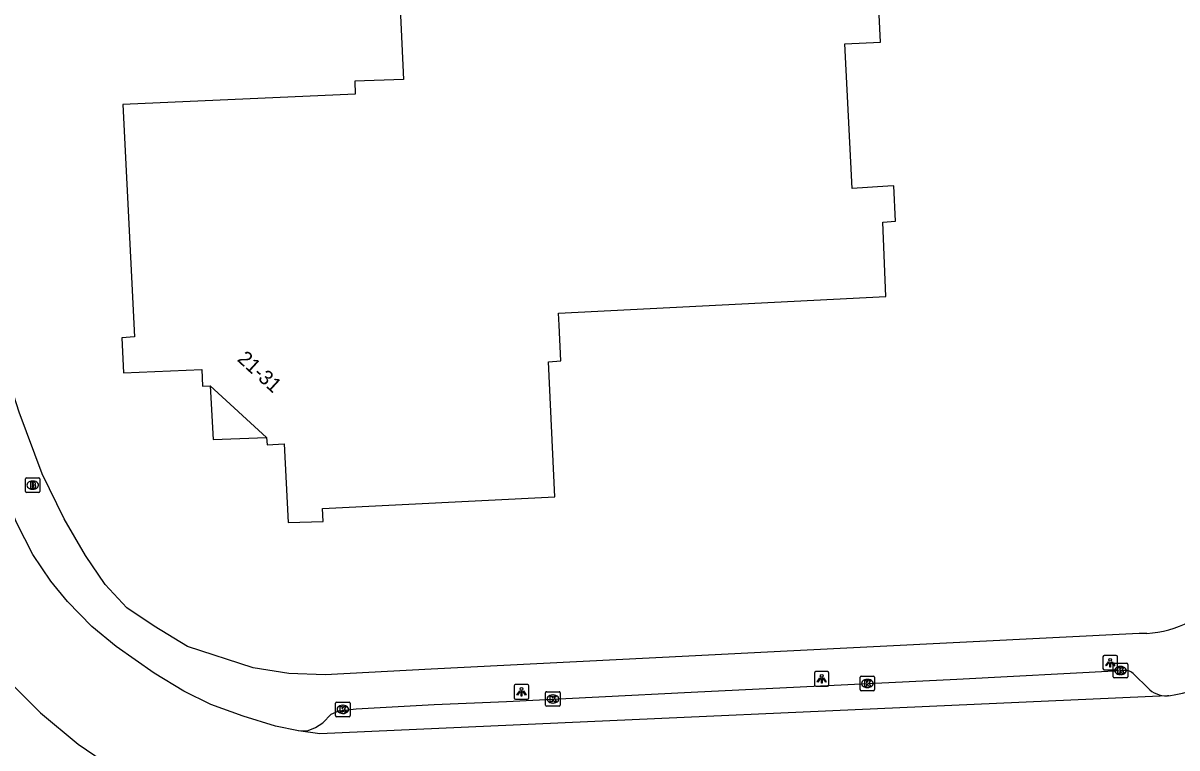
# Model space of a CAD drawing. Extents: x 157692 to 159670, y 381454 to 383289.
# Drawn here: x 157922.9 to 158002.1, y 381592.8 to 381642.5 of the extents above; entities that cross this region are included whole.
import ezdxf

# ---------------------------------------------------------------- set-up
doc = ezdxf.new("R2010")
doc.units = 0
for name, color, linetype in [('IMGEO_Brandkraan', 7, 'Continuous'), ('IMGEO_Kolk', 7, 'Continuous'), ('IMGEO_Lichtpunt', 7, 'Continuous'), ('IMGEO_Pand', 7, 'Continuous'), ('IMGEO_Pand_nummerreeks', 7, 'Continuous'), ('IMGEO_Pand_overbouw', 7, 'Continuous'), ('IMGEO_Rijbaan_lokaal_gesloten', 7, 'Continuous'), ('IMGEO_Voetpad_open', 7, 'Continuous')]:
    doc.layers.add(name, color=color, linetype=linetype)

msp = doc.modelspace()

# ---------------------------------------------------------------- linework, layer by layer
at = {"layer": 'IMGEO_Brandkraan'}
for p, q in [((157923.045, 381610.378), (157923.045, 381611.23)), ((157923.12, 381611.304), (157923.972, 381611.304)), ((157923.533, 381611.084), (157923.558, 381611.084)), ((157924.046, 381611.23), (157924.046, 381610.378)), ((157923.972, 381610.304), (157923.12, 381610.304)), ((157923.556, 381610.524), (157923.531, 381610.524))]:
    msp.add_line(p, q, dxfattribs=at)
for points in [[(157923.045, 381610.378), (157923.045, 381611.23)], [(157923.12, 381611.304), (157923.972, 381611.304)], [(157923.393, 381611.004), (157923.393, 381610.604), (157923.606, 381610.604)], [(157923.624, 381611.004), (157923.393, 381611.004)], [(157923.572, 381610.923), (157923.518, 381610.923), (157923.518, 381610.847)], [(157923.518, 381610.847), (157923.571, 381610.847)], [(157923.58, 381610.771), (157923.518, 381610.771), (157923.518, 381610.69)], [(157924.046, 381611.23), (157924.046, 381610.378)], [(157923.972, 381610.304), (157923.12, 381610.304)], [(157923.518, 381610.69), (157923.58, 381610.69)]]:
    msp.add_lwpolyline(points, dxfattribs=at)
for centre, radius, start, end in [((157923.122, 381611.228), 0.0765, 91.55205, 178.44795), ((157923.122, 381611.228), 0.0765, 91.55205, 178.44795), ((157923.573, 381610.885), 0.0379, 267.82845, 90.93552), ((157923.581, 381610.73), 0.0404, 269.87594, 90.50774), ((157923.628, 381610.859), 0.145, 59.4692, 91.53667), ((157923.653, 381610.906), 0.0922, 285.51372, 58.15012), ((157923.658, 381610.714), 0.105, 301.31148, 78.98903), ((157923.97, 381611.228), 0.0765, 1.55205, 88.44795), ((157923.97, 381611.228), 0.0765, 1.55205, 88.44795), ((157923.122, 381610.38), 0.0765, 181.55205, 268.44795), ((157923.122, 381610.38), 0.0765, 181.55205, 268.44795), ((157923.612, 381610.855), 0.251, 268.66757, 293.53466), ((157923.97, 381610.38), 0.0765, 271.55205, 358.44795), ((157923.97, 381610.38), 0.0765, 271.55205, 358.44795)]:
    msp.add_arc(centre, radius, start, end, dxfattribs=at)
for centre, major_axis, ratio, start_param, end_param in [((157923.532, 381610.804), (-0.387, 0.002), 0.722429, 4.712389, 7.853982), ((157923.557, 381610.804), (-0.39, 0.002), 0.717154, 1.570796, 4.712389)]:
    msp.add_ellipse(centre, major_axis=major_axis, ratio=ratio, start_param=start_param, end_param=end_param, dxfattribs=at)
at = {"layer": 'IMGEO_Kolk'}
for p, q in [((157997.701, 381597.653), (157997.701, 381598.505)), ((157997.776, 381598.579), (157998.628, 381598.579)), ((157998.189, 381598.359), (157998.214, 381598.359)), ((157998.702, 381598.505), (157998.702, 381597.653)), ((157980.327, 381596.768), (157980.327, 381597.62)), ((157980.402, 381597.694), (157981.254, 381597.694)), ((157980.815, 381597.474), (157980.84, 381597.474)), ((157981.328, 381597.62), (157981.328, 381596.768)), ((157998.628, 381597.579), (157997.776, 381597.579)), ((157998.212, 381597.799), (157998.187, 381597.799)), ((157958.749, 381595.703), (157958.749, 381596.555)), ((157958.824, 381596.629), (157959.676, 381596.629)), ((157959.75, 381596.555), (157959.75, 381595.703)), ((157981.254, 381596.694), (157980.402, 381596.694)), ((157980.838, 381596.914), (157980.813, 381596.914)), ((157944.331, 381594.987), (157944.331, 381595.839)), ((157944.406, 381595.913), (157945.258, 381595.913)), ((157944.819, 381595.693), (157944.844, 381595.693)), ((157945.332, 381595.839), (157945.332, 381594.987)), ((157959.26, 381595.849), (157959.235, 381595.849)), ((157959.237, 381596.409), (157959.262, 381596.409)), ((157945.258, 381594.913), (157944.406, 381594.913)), ((157944.842, 381595.133), (157944.817, 381595.133)), ((157959.676, 381595.629), (157958.824, 381595.629))]:
    msp.add_line(p, q, dxfattribs=at)
for points in [[(157997.701, 381597.653), (157997.701, 381598.505)], [(157997.776, 381598.579), (157998.628, 381598.579)], [(157998.022, 381598.279), (157998.145, 381598.279), (157998.145, 381598.128), (157998.275, 381598.279), (157998.439, 381598.279), (157998.293, 381598.128), (157998.446, 381597.879), (157998.294, 381597.879), (157998.209, 381598.043), (157998.145, 381597.976), (157998.145, 381597.879), (157998.022, 381597.879), (157998.022, 381598.279)], [(157998.702, 381598.505), (157998.702, 381597.653)], [(157980.327, 381596.768), (157980.327, 381597.62)], [(157980.402, 381597.694), (157981.254, 381597.694)], [(157980.648, 381597.394), (157980.771, 381597.394), (157980.771, 381597.243), (157980.901, 381597.394), (157981.065, 381597.394), (157980.919, 381597.243), (157981.072, 381596.994), (157980.92, 381596.994), (157980.835, 381597.158), (157980.771, 381597.091), (157980.771, 381596.994), (157980.648, 381596.994), (157980.648, 381597.394)], [(157981.328, 381597.62), (157981.328, 381596.768)], [(157998.628, 381597.579), (157997.776, 381597.579)], [(157958.749, 381595.703), (157958.749, 381596.555)], [(157958.824, 381596.629), (157959.676, 381596.629)], [(157959.75, 381596.555), (157959.75, 381595.703)], [(157981.254, 381596.694), (157980.402, 381596.694)], [(157944.331, 381594.987), (157944.331, 381595.839)], [(157944.406, 381595.913), (157945.258, 381595.913)], [(157945.332, 381595.839), (157945.332, 381594.987)], [(157959.07, 381596.329), (157959.193, 381596.329), (157959.193, 381596.178), (157959.323, 381596.329), (157959.487, 381596.329), (157959.341, 381596.178), (157959.494, 381595.929), (157959.342, 381595.929), (157959.257, 381596.093), (157959.193, 381596.026), (157959.193, 381595.929), (157959.07, 381595.929), (157959.07, 381596.329)], [(157945.258, 381594.913), (157944.406, 381594.913)], [(157944.652, 381595.613), (157944.775, 381595.613), (157944.775, 381595.462), (157944.905, 381595.613), (157945.069, 381595.613), (157944.923, 381595.462), (157945.076, 381595.213), (157944.924, 381595.213), (157944.839, 381595.377), (157944.775, 381595.31), (157944.775, 381595.213), (157944.652, 381595.213), (157944.652, 381595.613)], [(157959.676, 381595.629), (157958.824, 381595.629)]]:
    msp.add_lwpolyline(points, dxfattribs=at)
for centre, start, end in [((157997.778, 381598.503), 91.55205, 178.44795), ((157997.778, 381598.503), 91.55205, 178.44795), ((157998.626, 381598.503), 1.55205, 88.44795), ((157998.626, 381598.503), 1.55205, 88.44795), ((157980.404, 381597.618), 91.55205, 178.44795), ((157980.404, 381597.618), 91.55205, 178.44795), ((157981.252, 381597.618), 1.55205, 88.44795), ((157981.252, 381597.618), 1.55205, 88.44795), ((157997.778, 381597.655), 181.55205, 268.44795), ((157997.778, 381597.655), 181.55205, 268.44795), ((157998.626, 381597.655), 271.55205, 358.44795), ((157998.626, 381597.655), 271.55205, 358.44795), ((157958.826, 381596.553), 91.55205, 178.44795), ((157958.826, 381596.553), 91.55205, 178.44795), ((157959.674, 381596.553), 1.55205, 88.44795), ((157959.674, 381596.553), 1.55205, 88.44795), ((157980.404, 381596.77), 181.55205, 268.44795), ((157980.404, 381596.77), 181.55205, 268.44795), ((157981.252, 381596.77), 271.55205, 358.44795), ((157981.252, 381596.77), 271.55205, 358.44795), ((157944.408, 381595.837), 91.55205, 178.44795), ((157944.408, 381595.837), 91.55205, 178.44795), ((157945.256, 381595.837), 1.55205, 88.44795), ((157945.256, 381595.837), 1.55205, 88.44795), ((157958.826, 381595.705), 181.55205, 268.44795), ((157958.826, 381595.705), 181.55205, 268.44795), ((157959.674, 381595.705), 271.55205, 358.44795), ((157959.674, 381595.705), 271.55205, 358.44795), ((157944.408, 381594.989), 181.55205, 268.44795), ((157944.408, 381594.989), 181.55205, 268.44795), ((157945.256, 381594.989), 271.55205, 358.44795), ((157945.256, 381594.989), 271.55205, 358.44795)]:
    msp.add_arc(centre, 0.0765, start, end, dxfattribs=at)
for centre, major_axis, ratio, start_param, end_param in [((157998.188, 381598.079), (-0.387, 0.002), 0.722429, 4.712389, 7.853982), ((157998.213, 381598.079), (-0.39, 0.002), 0.717154, 1.570796, 4.712389), ((157980.814, 381597.194), (-0.387, 0.002), 0.722429, 4.712389, 7.853982), ((157980.839, 381597.194), (-0.39, 0.002), 0.717154, 1.570796, 4.712389), ((157944.818, 381595.413), (-0.387, 0.002), 0.722429, 4.712389, 7.853982), ((157944.843, 381595.413), (-0.39, 0.002), 0.717154, 1.570796, 4.712389), ((157959.236, 381596.129), (-0.387, 0.002), 0.722429, 4.712389, 7.853982), ((157959.261, 381596.129), (-0.39, 0.002), 0.717154, 1.570796, 4.712389)]:
    msp.add_ellipse(centre, major_axis=major_axis, ratio=ratio, start_param=start_param, end_param=end_param, dxfattribs=at)
at = {"layer": 'IMGEO_Lichtpunt'}
for p, q in [((157996.995, 381599.018), (157996.995, 381598.211)), ((157996.995, 381599.018), (157996.995, 381598.211)), ((157997.897, 381599.113), (157997.089, 381599.113)), ((157997.897, 381599.113), (157997.089, 381599.113)), ((157997.991, 381598.211), (157997.991, 381599.018)), ((157997.991, 381598.211), (157997.991, 381599.018)), ((157997.089, 381598.117), (157997.897, 381598.117)), ((157997.089, 381598.117), (157997.897, 381598.117)), ((157977.197, 381597.909), (157977.197, 381597.102)), ((157977.197, 381597.909), (157977.197, 381597.102)), ((157978.099, 381598.004), (157977.291, 381598.004)), ((157978.099, 381598.004), (157977.291, 381598.004)), ((157978.193, 381597.102), (157978.193, 381597.909)), ((157978.193, 381597.102), (157978.193, 381597.909)), ((157956.595, 381597.02), (157956.595, 381596.213)), ((157956.595, 381597.02), (157956.595, 381596.213)), ((157957.497, 381597.115), (157956.689, 381597.115)), ((157957.497, 381597.115), (157956.689, 381597.115)), ((157957.591, 381596.213), (157957.591, 381597.02)), ((157957.591, 381596.213), (157957.591, 381597.02)), ((157977.291, 381597.008), (157978.099, 381597.008)), ((157977.291, 381597.008), (157978.099, 381597.008)), ((157956.689, 381596.119), (157957.497, 381596.119)), ((157956.689, 381596.119), (157957.497, 381596.119))]:
    msp.add_line(p, q, dxfattribs=at)
for points in [[(157997.369, 381598.682), (157997.408, 381598.654), (157997.22, 381598.392), (157997.182, 381598.419), (157997.369, 381598.682)], [(157997.471, 381598.634), (157997.518, 381598.634), (157997.518, 381598.312), (157997.471, 381598.312), (157997.471, 381598.634)], [(157997.581, 381598.654), (157997.619, 381598.681), (157997.806, 381598.419), (157997.767, 381598.391), (157997.581, 381598.654)], [(157977.571, 381597.573), (157977.61, 381597.545), (157977.422, 381597.283), (157977.384, 381597.31), (157977.571, 381597.573)], [(157977.673, 381597.525), (157977.72, 381597.525), (157977.72, 381597.203), (157977.673, 381597.203), (157977.673, 381597.525)], [(157977.783, 381597.545), (157977.821, 381597.572), (157978.008, 381597.31), (157977.969, 381597.282), (157977.783, 381597.545)], [(157956.969, 381596.684), (157957.008, 381596.656), (157956.82, 381596.394), (157956.782, 381596.421), (157956.969, 381596.684)], [(157957.071, 381596.636), (157957.118, 381596.636), (157957.118, 381596.314), (157957.071, 381596.314), (157957.071, 381596.636)], [(157957.181, 381596.656), (157957.219, 381596.683), (157957.406, 381596.421), (157957.367, 381596.393), (157957.181, 381596.656)]]:
    msp.add_lwpolyline(points, dxfattribs=at)
for centre in [(157997.494, 381598.816), (157977.696, 381597.707), (157957.094, 381596.818)]:
    msp.add_circle(centre, 0.0994, dxfattribs=at)
for centre, start, end in [((157997.089, 381599.018), 90, 180), ((157997.089, 381599.018), 90, 180), ((157997.897, 381599.018), 0, 90), ((157997.897, 381599.018), 0, 90), ((157997.089, 381598.211), 180, 270), ((157997.089, 381598.211), 180, 270), ((157997.897, 381598.211), 270, 0), ((157997.897, 381598.211), 270, 360), ((157977.291, 381597.909), 90, 180), ((157977.291, 381597.909), 90, 180), ((157978.099, 381597.909), 0, 90), ((157978.099, 381597.909), 0, 90), ((157956.689, 381597.02), 90, 180), ((157956.689, 381597.02), 90, 180), ((157957.497, 381597.02), 0, 90), ((157957.497, 381597.02), 0, 90), ((157977.291, 381597.102), 180, 270), ((157977.291, 381597.102), 180, 270), ((157978.099, 381597.102), 270, 0), ((157978.099, 381597.102), 270, 360), ((157956.689, 381596.213), 180, 270), ((157956.689, 381596.213), 180, 270), ((157957.497, 381596.213), 270, 0), ((157957.497, 381596.213), 270, 360)]:
    msp.add_arc(centre, 0.0946, start, end, dxfattribs=at)
at = {"layer": 'IMGEO_Pand'}
for points in [[(157982.763, 381628.908), (157982.646, 381631.35), (157982.232, 381631.323), (157979.774, 381631.161), (157979.28, 381641.078), (157981.737, 381641.204), (157981.178, 381652.486)], [(157948.429, 381650.907), (157948.99, 381638.639), (157945.647, 381638.532), (157945.679, 381637.634), (157929.724, 381636.919), (157930.545, 381620.976), (157929.656, 381620.921), (157929.771, 381618.502), (157935.146, 381618.731), (157935.205, 381617.594), (157935.72, 381617.615), (157939.592, 381614.082), (157939.637, 381613.565), (157940.808, 381613.63), (157941.077, 381608.244), (157943.481, 381608.314), (157943.445, 381609.208), (157959.38, 381610.007), (157958.942, 381619.275), (157959.791, 381619.336), (157959.676, 381621.775), (157959.636, 381622.61), (157982.085, 381623.74), (157981.885, 381628.842), (157982.763, 381628.908)]]:
    msp.add_lwpolyline(points, dxfattribs=at)
at = {"layer": 'IMGEO_Pand_overbouw'}
msp.add_lwpolyline([(157939.592, 381614.082), (157935.72, 381617.615), (157935.931, 381613.941)], close=True, dxfattribs=at)
at = {"layer": 'IMGEO_Rijbaan_lokaal_gesloten'}
for points in [[(157941.787, 381593.953), (157940.201, 381594.263), (157937.982, 381594.948), (157935.779, 381595.742), (157933.913, 381596.673), (157931.88, 381597.897), (157929.284, 381599.727), (157927.609, 381601.111), (157925.926, 381602.819), (157924.801, 381604.213), (157923.565, 381606.033), (157922.451, 381608.183), (157920.957, 381611.715), (157919.038, 381616.874), (157916.313, 381625.205), (157914.556, 381631.129), (157913.243, 381635.916), (157911.724, 381642.343)], [(157921.704, 381597.546), (157924.075, 381595.18), (157926.673, 381593.026), (157928.952, 381591.478)], [(158001.415, 381596.346), (157943.247, 381593.747), (157941.787, 381593.953)], [(158001.519, 381596.351), (158001.415, 381596.346)]]:
    msp.add_lwpolyline(points, dxfattribs=at)
msp.add_arc((158000.12, 381606.109), 9.857, 278.15929, 321.75758, dxfattribs=at)
at = {"layer": 'IMGEO_Voetpad_open'}
for points in [[(158000, 381600.627), (157999.488, 381600.615), (157975.32, 381599.4), (157968.585, 381599.074), (157950.884, 381598.177), (157943.627, 381597.785), (157941.118, 381597.881), (157938.678, 381598.262), (157934.17, 381599.736), (157931.89, 381601.119), (157930.007, 381602.373), (157928.512, 381603.995), (157927.171, 381605.97), (157925.712, 381608.5), (157924.2, 381611.589), (157922.624, 381615.817), (157918.988, 381627.119), (157917.13, 381633.664), (157914.922, 381642.995)], [(157941.787, 381593.953), (157942.441, 381593.968), (157942.949, 381594.159), (157943.448, 381594.5), (157944.019, 381595.083), (157944.557, 381595.318), (157945.747, 381595.46), (157951.089, 381595.738), (157956.057, 381595.962), (157968.73, 381596.605), (157986.967, 381597.489), (157998.198, 381598.078), (157998.421, 381598.082)], [(157999.14, 381597.809), (158000.068, 381596.883)]]:
    msp.add_lwpolyline(points, dxfattribs=at)
for centre, radius, start, end in [((157999.568, 381608.009), 7.395, 273.3508, 320.84628), ((157998.487, 381597.174), 0.911, 44.23736, 94.1797), ((158001.387, 381598.234), 1.888, 225.68425, 270.845)]:
    msp.add_arc(centre, radius, start, end, dxfattribs=at)

# ---------------------------------------------------------------- texts
at = {"layer": 'IMGEO_Pand_nummerreeks'}
msp.add_text('21-31', height=1, rotation=317.62116, dxfattribs=at).set_placement((157937.529, 381619.376))

doc.saveas('drawing.dxf')
